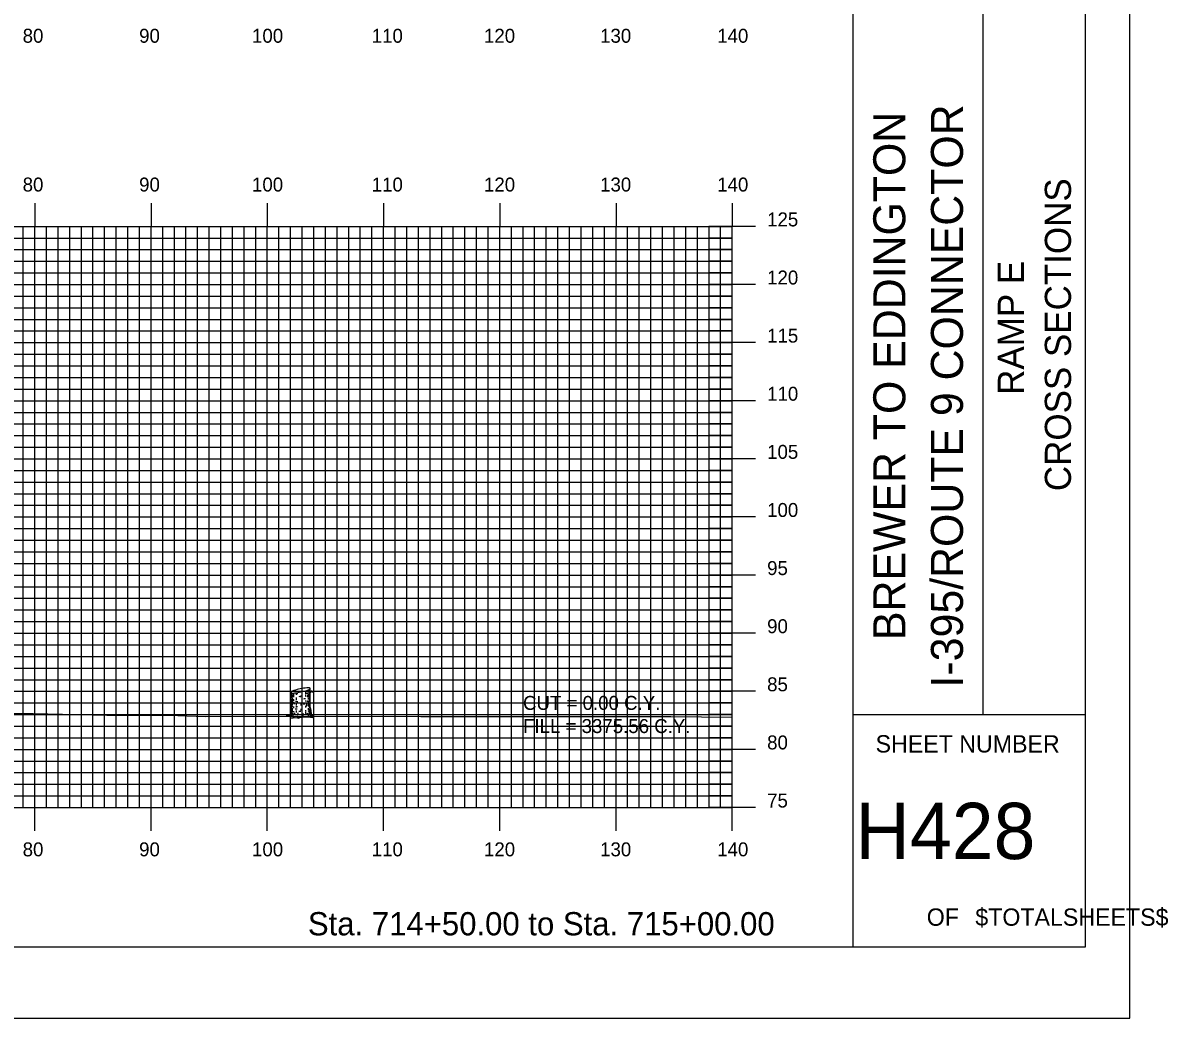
# Model space of a CAD drawing. Extents: x 856084 to 856427, y 364366 to 364586.
# Drawn here: x 856328.8 to 856427.3, y 364365.7 to 364451.3 of the extents above; entities that cross this region are included whole.
import ezdxf

# ---------------------------------------------------------------- set-up
doc = ezdxf.new("R2010")
doc.units = 0
for name, color, linetype in [('BORDER', 7, 'Continuous'), ('D_Text_Standard', 7, 'Continuous'), ('H_V ANNOTATION', 7, 'Continuous'), ('M_Trees_Conifer_Pay', 7, 'Continuous'), ('MAJOR', 7, 'Continuous'), ('MINOR', 7, 'Continuous'), ('PLOT BOUNDARY', 7, 'Continuous'), ('S_Roadway_Centerline', 7, 'Continuous')]:
    doc.layers.add(name, color=color, linetype=linetype)

msp = doc.modelspace()

# ---------------------------------------------------------------- linework, layer by layer
at = {"layer": 'BORDER'}
for p, q in [((856400.196, 364371.787), (856400.196, 364581.787)), ((856411.378, 364391.793), (856411.378, 364461.793)), ((856400.196, 364391.793), (856420.196, 364391.793))]:
    msp.add_line(p, q, dxfattribs=at)
msp.add_lwpolyline([(856100.196, 364371.787), (856420.196, 364371.787), (856420.196, 364581.787), (856100.196, 364581.787)], close=True, dxfattribs=at)
at = {"layer": 'M_Trees_Conifer_Pay'}
for p, q in [((856353.421, 364393.959), (856353.421, 364393.796)), ((856353.492, 364392.384), (856353.492, 364394.031)), ((856351.828, 364391.974), (856351.828, 364393.696)), ((856351.876, 364393.658), (856351.876, 364393.187)), ((856351.876, 364393.123), (856351.876, 364392.814)), ((856351.934, 364393.647), (856351.934, 364393.549)), ((856351.934, 364393.475), (856351.934, 364393.271)), ((856351.934, 364393.213), (856351.934, 364393.014)), ((856351.934, 364392.967), (856351.934, 364392.631)), ((856352.059, 364393.639), (856352.059, 364393.407)), ((856352.059, 364393.366), (856352.059, 364393.292)), ((856352.279, 364393.659), (856352.279, 364393.491)), ((856352.279, 364393.255), (856352.279, 364393.018)), ((856352.685, 364393.428), (856352.685, 364393.333)), ((856353.075, 364393.701), (856353.075, 364393.502)), ((856353.075, 364393.444), (856353.075, 364393.356)), ((856353.075, 364393.008), (856353.075, 364392.903)), ((856353.304, 364393.898), (856353.304, 364393.675)), ((856353.304, 364393.586), (856353.304, 364393.539)), ((856353.304, 364393.203), (856353.304, 364393.072)), ((856353.304, 364392.961), (856353.304, 364392.851)), ((856353.361, 364393.403), (856353.309, 364393.343)), ((856353.421, 364393.728), (856353.421, 364393.6)), ((856353.421, 364393.413), (856353.421, 364393.077)), ((856353.421, 364393.041), (856353.421, 364392.878)), ((856351.876, 364392.767), (856351.876, 364392.275)), ((856351.876, 364392.221), (856351.876, 364391.974)), ((856351.934, 364392.577), (856351.934, 364392.442)), ((856351.934, 364392.343), (856351.934, 364391.964)), ((856352.059, 364392.888), (856352.059, 364392.75)), ((856352.059, 364392.478), (856352.059, 364392.337)), ((856352.059, 364392.075), (856352.059, 364391.98)), ((856352.279, 364392.773), (856352.279, 364392.621)), ((856352.279, 364392.577), (856352.279, 364392.404)), ((856352.279, 364392.127), (856352.279, 364391.974)), ((856352.685, 364392.814), (856352.685, 364392.74)), ((856352.685, 364392.715), (856352.685, 364392.567)), ((856352.685, 364392.275), (856352.685, 364392.122)), ((856353.075, 364392.536), (856353.075, 364392.39)), ((856353.075, 364392.157), (856353.075, 364392.069)), ((856353.304, 364392.715), (856353.304, 364392.573)), ((856353.304, 364392.346), (856353.304, 364392.174)), ((856353.421, 364392.831), (856353.421, 364392.614)), ((856353.421, 364392.583), (856353.421, 364392.509)), ((856353.421, 364392.469), (856353.421, 364392.295)), ((856352.059, 364391.581), (856352.222, 364391.644)), ((856352.496, 364391.516), (856352.37, 364391.581))]:
    msp.add_line(p, q, dxfattribs=at)
for points in [[(856352.008, 364393.001), (856352.002, 364393.096), (856352.045, 364393.073), (856352.045, 364392.979)], [(856353.276, 364393.491), (856353.245, 364393.407), (856353.241, 364393.339), (856353.272, 364393.276)], [(856353.309, 364393.529), (856353.346, 364393.455), (856353.393, 364393.512), (856353.451, 364393.58), (856353.544, 364393.774), (856353.608, 364393.821), (856353.639, 364393.827)], [(856353.324, 364393.276), (856353.361, 364393.403), (856353.424, 364393.518), (856353.455, 364393.586), (856353.524, 364393.732)], [(856353.538, 364393.762), (856353.614, 364393.77), (856353.686, 364393.671)], [(856353.492, 364392.384), (856353.544, 364392.122), (856353.56, 364391.848), (856353.618, 364391.723), (856353.754, 364391.692), (856353.523, 364391.655), (856353.523, 364391.655), (856353.529, 364391.608), (856353.777, 364391.513), (856353.502, 364391.53), (856353.147, 364391.55), (856352.825, 364391.539), (856352.832, 364391.622), (856352.683, 364391.539), (856352.496, 364391.516), (856352.521, 364391.449), (856352.253, 364391.492), (856352.033, 364391.465), (856351.74, 364391.482), (856352.029, 364391.539), (856352.059, 364391.581), (856351.897, 364391.638), (856351.66, 364391.649), (856351.419, 364391.649), (856351.761, 364391.707), (856351.802, 364391.787), (856351.828, 364391.974)], [(856353.082, 364391.991), (856353.093, 364391.865), (856353.167, 364391.822)], [(856353.147, 364392.602), (856353.159, 364392.526), (856353.206, 364392.536), (856353.194, 364392.703)], [(856353.319, 364392.096), (856353.393, 364391.991), (856353.398, 364391.818), (856353.523, 364391.655)], [(856353.418, 364392.241), (856353.424, 364392.096), (856353.471, 364392.028), (856353.482, 364391.828)], [(856351.876, 364391.927), (856351.855, 364391.848), (856351.835, 364391.754)], [(856351.954, 364391.906), (856351.96, 364391.791), (856351.907, 364391.702), (856351.897, 364391.638)], [(856352.117, 364391.933), (856352.117, 364391.801), (856352.029, 364391.702)], [(856352.344, 364391.692), (856352.411, 364391.787), (856352.438, 364391.927)], [(856352.832, 364391.622), (856352.906, 364391.764), (856352.916, 364391.865)], [(856353.361, 364391.602), (856353.346, 364391.74), (856353.272, 364391.869)]]:
    msp.add_lwpolyline(points, dxfattribs=at)
for centre, radius, start, end in [((856353.684, 364388.928), 5.179, 101.7194, 108.05939), ((856353.684, 364388.928), 5.179, 95.37941, 101.7194), ((856353.274, 364393.286), 0.802, 79.2194, 95.37941), ((856352.994, 364394.637), 0.802, 288.05939, 304.2194), ((856353.377, 364393.827), 0.251, 71.05013, 79.2194), ((856353.304, 364394.181), 0.251, 304.2194, 312.38868), ((856353.432, 364393.987), 0.0817, 56.7194, 71.05013), ((856353.417, 364394.056), 0.0817, 312.38868, 326.7194), ((856353.448, 364394.011), 0.0527, 46.92298, 56.7194), ((856353.462, 364394.027), 0.0314, 34.2194, 46.92298), ((856353.442, 364394.04), 0.0527, 326.7194, 336.51582), ((856353.466, 364394.03), 0.0264, 23.40735, 34.2194), ((856353.461, 364394.032), 0.0314, 336.51582, 349.2194), ((856353.47, 364394.031), 0.0226, 11.7194, 23.40735), ((856353.47, 364394.031), 0.0226, 0.03145, 11.7194), ((856353.466, 364394.031), 0.0264, 349.2194, 0.03145), ((856351.861, 364393.517), 0.0334, 163.94846, 180), ((856351.861, 364393.517), 0.0334, 180, 196.05154), ((856351.861, 364393.07), 0.0334, 163.94846, 180), ((856351.861, 364393.07), 0.0334, 180, 196.05154), ((856351.86, 364393.694), 0.0314, 156.51582, 169.2194), ((856351.855, 364393.695), 0.0264, 169.2194, 180.03145), ((856351.851, 364393.695), 0.0226, 180.03145, 191.7194), ((856351.851, 364393.695), 0.0226, 191.7194, 203.40735), ((856351.871, 364393.52), 0.0441, 196.05154, 210), ((856351.871, 364393.073), 0.0441, 196.05154, 210), ((856351.855, 364393.697), 0.0264, 203.40735, 214.2194), ((856351.879, 364393.686), 0.0527, 146.7194, 156.51582), ((856351.859, 364393.7), 0.0314, 214.2194, 226.92298), ((856351.887, 364393.529), 0.0624, 210, 228.74941), ((856351.887, 364393.083), 0.0624, 210, 228.74941), ((856351.904, 364393.67), 0.0817, 132.38868, 146.7194), ((856351.873, 364393.715), 0.0527, 226.92298, 236.7194), ((856351.889, 364393.739), 0.0817, 236.7194, 251.05013), ((856351.959, 364393.612), 0.172, 228.74941, 240), ((856351.959, 364393.165), 0.172, 228.74941, 240), ((856352.018, 364393.545), 0.251, 124.2194, 132.38868), ((856351.944, 364393.899), 0.251, 251.05013, 259.2194), ((856352.158, 364393.957), 0.571, 240, 240.33672), ((856352.158, 364393.51), 0.571, 240, 240.33672), ((856352.16, 364393.746), 0.571, 240, 247.05866), ((856352.327, 364393.09), 0.802, 108.05939, 124.2194), ((856352.047, 364394.44), 0.802, 259.2194, 275.37941), ((856352.158, 364393.957), 0.571, 246.85973, 257.98457), ((856351.637, 364398.798), 5.179, 275.37941, 281.7194), ((856352.659, 364397.028), 4.124, 264.08098, 266.66759), ((856352.661, 364397.707), 4.124, 264.6955, 266.73309), ((856352.659, 364397.475), 4.124, 268.07512, 270), ((856352.659, 364397.475), 4.124, 270, 270.35814), ((856351.637, 364398.798), 5.179, 281.7194, 288.05939), ((856352.661, 364397.264), 4.124, 273.70524, 275.95043), ((856352.659, 364397.475), 4.124, 275.78493, 277.05584), ((856352.661, 364397.707), 4.124, 276.23804, 278.1032), ((856352.659, 364397.028), 4.124, 277.61247, 278.1032), ((856353.16, 364393.51), 0.571, 278.1032, 286.92962), ((856353.162, 364394.19), 0.571, 278.1032, 284.36665), ((856353.162, 364394.344), 0.571, 284.43166, 292.41325), ((856353.161, 364393.746), 0.571, 284.44928, 297.04285), ((856353.162, 364394.19), 0.571, 297.0237, 300), ((856353.16, 364393.51), 0.571, 297.18959, 300), ((856353.359, 364393.165), 0.172, 300, 311.25059), ((856353.361, 364393.999), 0.172, 300, 311.25059), ((856353.361, 364393.845), 0.172, 300, 311.25059), ((856353.432, 364393.083), 0.0624, 311.25059, 330), ((856353.433, 364393.917), 0.0624, 311.25059, 330), ((856353.433, 364393.762), 0.0624, 311.25059, 330), ((856353.448, 364393.073), 0.0441, 330, 343.94846), ((856353.449, 364393.908), 0.0441, 330, 343.94846), ((856353.449, 364393.753), 0.0441, 330, 343.94846), ((856353.458, 364393.07), 0.0334, 343.94846, 354.21506), ((856353.459, 364393.905), 0.0334, 343.94846, 354.21506), ((856353.459, 364393.75), 0.0334, 343.94846, 354.21506), ((856353.459, 364393.306), 0.0334, 343.94846, 354.21506), ((856351.861, 364392.86), 0.0334, 163.94846, 180), ((856351.861, 364392.86), 0.0334, 180, 196.05154), ((856351.861, 364392.624), 0.0334, 163.94846, 180), ((856351.861, 364392.624), 0.0334, 180, 196.05154), ((856351.861, 364392.426), 0.0334, 163.94846, 180), ((856351.861, 364392.23), 0.0334, 163.94846, 180), ((856351.861, 364392.23), 0.0334, 180, 196.05154), ((856351.861, 364392.01), 0.0334, 163.94846, 180), ((856351.861, 364392.01), 0.0334, 180, 196.05154), ((856351.871, 364392.863), 0.0441, 196.05154, 210), ((856351.871, 364392.627), 0.0441, 196.05154, 210), ((856351.871, 364392.233), 0.0441, 196.05154, 210), ((856351.871, 364392.013), 0.0441, 196.05154, 210), ((856351.887, 364392.873), 0.0624, 210, 228.74941), ((856351.887, 364392.636), 0.0624, 210, 228.74941), ((856351.887, 364392.243), 0.0624, 210, 228.74941), ((856351.887, 364392.022), 0.0624, 210, 228.74941), ((856351.959, 364392.955), 0.172, 228.74941, 240), ((856351.959, 364392.718), 0.172, 228.74941, 240), ((856351.959, 364392.325), 0.172, 228.74941, 240), ((856351.959, 364392.105), 0.172, 228.74941, 240), ((856352.158, 364393.3), 0.571, 240, 246.85973), ((856352.158, 364393.063), 0.571, 240, 246.85973), ((856352.148, 364392.872), 0.571, 241.23686, 248.02677), ((856352.158, 364392.67), 0.571, 240, 246.85973), ((856352.158, 364392.45), 0.571, 240, 244.53138), ((856352.158, 364393.3), 0.571, 259.27072, 261.8968), ((856352.659, 364396.818), 4.124, 261.8968, 263.14738), ((856352.659, 364396.383), 4.124, 263.49906, 265.83975), ((856352.659, 364396.581), 4.124, 264.71603, 266.31934), ((856352.659, 364396.188), 4.124, 267.81166, 270), ((856352.659, 364396.818), 4.124, 270, 270.35814), ((856352.659, 364396.188), 4.124, 270, 270.13279), ((856352.659, 364396.818), 4.124, 273.14934, 275.45691), ((856352.659, 364396.188), 4.124, 275.78493, 276.78961), ((856353.16, 364393.063), 0.571, 285.39827, 297.18959), ((856353.16, 364392.67), 0.571, 288.50673, 297.27208), ((856353.16, 364392.866), 0.571, 289.29072, 300), ((856353.16, 364393.3), 0.571, 297.18959, 300), ((856353.359, 364392.955), 0.172, 300, 311.25059), ((856353.359, 364392.521), 0.172, 300, 311.25059), ((856353.359, 364392.105), 0.172, 300, 311.25059), ((856353.432, 364392.873), 0.0624, 311.25059, 330), ((856353.432, 364392.438), 0.0624, 311.25059, 330), ((856353.432, 364392.022), 0.0624, 311.25059, 330), ((856353.448, 364392.863), 0.0441, 330, 343.94846), ((856353.448, 364392.429), 0.0441, 330, 343.94846), ((856353.448, 364392.013), 0.0441, 330, 343.94846), ((856353.458, 364392.86), 0.0334, 343.94846, 354.21506), ((856353.458, 364392.426), 0.0334, 343.94846, 354.21506), ((856353.458, 364392.01), 0.0334, 343.94846, 354.21506), ((856352.659, 364395.967), 4.124, 262.44379, 263.51202), ((856352.659, 364395.967), 4.124, 277.36842, 278.1032), ((856353.16, 364392.45), 0.571, 278.1032, 281.63703)]:
    msp.add_arc(centre, radius, start, end, dxfattribs=at)
at = {"layer": 'MAJOR'}
for p, q in [((856329.796, 364435.791), (856329.796, 364433.787)), ((856339.796, 364435.791), (856339.796, 364433.787)), ((856349.796, 364435.791), (856349.796, 364433.787)), ((856359.796, 364435.791), (856359.796, 364433.787)), ((856369.796, 364435.791), (856369.796, 364433.787)), ((856379.796, 364435.791), (856379.796, 364433.787)), ((856389.796, 364435.791), (856389.796, 364433.787)), ((856109.796, 364433.787), (856389.796, 364433.787)), ((856109.796, 364433.787), (856389.796, 364433.787)), ((856329.796, 364383.787), (856329.796, 364433.787)), ((856339.796, 364383.787), (856339.796, 364433.787)), ((856349.796, 364383.787), (856349.796, 364433.787)), ((856359.796, 364383.787), (856359.796, 364433.787)), ((856369.796, 364383.787), (856369.796, 364433.787)), ((856379.796, 364383.787), (856379.796, 364433.787)), ((856391.8, 364433.787), (856387.792, 364433.787)), ((856389.796, 364383.787), (856389.796, 364433.787)), ((856389.796, 364383.787), (856389.796, 364433.787)), ((856109.796, 364428.787), (856389.796, 364428.787)), ((856391.8, 364428.787), (856387.792, 364428.787)), ((856109.796, 364423.787), (856389.796, 364423.787)), ((856391.8, 364423.787), (856387.792, 364423.787)), ((856109.796, 364418.787), (856389.796, 364418.787)), ((856391.8, 364418.787), (856387.792, 364418.787)), ((856109.796, 364413.787), (856389.796, 364413.787)), ((856391.8, 364413.787), (856387.792, 364413.787)), ((856109.796, 364408.787), (856389.796, 364408.787)), ((856391.8, 364408.787), (856387.792, 364408.787)), ((856109.796, 364403.787), (856389.796, 364403.787)), ((856391.8, 364403.787), (856387.792, 364403.787)), ((856109.796, 364398.787), (856389.796, 364398.787)), ((856391.8, 364398.787), (856387.792, 364398.787)), ((856109.796, 364393.787), (856389.796, 364393.787)), ((856391.8, 364393.787), (856387.792, 364393.787)), ((856109.796, 364388.787), (856389.796, 364388.787)), ((856391.8, 364388.787), (856387.792, 364388.787)), ((856109.796, 364383.787), (856389.796, 364383.787)), ((856109.796, 364383.787), (856389.796, 364383.787)), ((856329.796, 364381.783), (856329.796, 364383.787)), ((856339.796, 364381.783), (856339.796, 364383.787)), ((856349.796, 364381.783), (856349.796, 364383.787)), ((856359.796, 364381.783), (856359.796, 364383.787)), ((856369.796, 364381.783), (856369.796, 364383.787)), ((856379.796, 364381.783), (856379.796, 364383.787)), ((856391.8, 364383.787), (856387.792, 364383.787)), ((856389.796, 364381.783), (856389.796, 364383.787))]:
    msp.add_line(p, q, dxfattribs=at)
at = {"layer": 'MINOR'}
for p, q in [((856328.796, 364383.787), (856328.796, 364433.787)), ((856330.796, 364383.787), (856330.796, 364433.787)), ((856331.796, 364383.787), (856331.796, 364433.787)), ((856332.796, 364383.787), (856332.796, 364433.787)), ((856333.796, 364383.787), (856333.796, 364433.787)), ((856334.796, 364383.787), (856334.796, 364433.787)), ((856335.796, 364383.787), (856335.796, 364433.787)), ((856336.796, 364383.787), (856336.796, 364433.787)), ((856337.796, 364383.787), (856337.796, 364433.787)), ((856338.796, 364383.787), (856338.796, 364433.787)), ((856340.796, 364383.787), (856340.796, 364433.787)), ((856341.796, 364383.787), (856341.796, 364433.787)), ((856342.796, 364383.787), (856342.796, 364433.787)), ((856343.796, 364383.787), (856343.796, 364433.787)), ((856344.796, 364383.787), (856344.796, 364433.787)), ((856345.796, 364383.787), (856345.796, 364433.787)), ((856346.796, 364383.787), (856346.796, 364433.787)), ((856347.796, 364383.787), (856347.796, 364433.787)), ((856348.796, 364383.787), (856348.796, 364433.787)), ((856350.796, 364383.787), (856350.796, 364433.787)), ((856351.796, 364383.787), (856351.796, 364433.787)), ((856352.796, 364383.787), (856352.796, 364433.787)), ((856353.796, 364383.787), (856353.796, 364433.787)), ((856354.796, 364383.787), (856354.796, 364433.787)), ((856355.796, 364383.787), (856355.796, 364433.787)), ((856356.796, 364383.787), (856356.796, 364433.787)), ((856357.796, 364383.787), (856357.796, 364433.787)), ((856358.796, 364383.787), (856358.796, 364433.787)), ((856360.796, 364383.787), (856360.796, 364433.787)), ((856361.796, 364383.787), (856361.796, 364433.787)), ((856362.796, 364383.787), (856362.796, 364433.787)), ((856363.796, 364383.787), (856363.796, 364433.787)), ((856364.796, 364383.787), (856364.796, 364433.787)), ((856365.796, 364383.787), (856365.796, 364433.787)), ((856366.796, 364383.787), (856366.796, 364433.787)), ((856367.796, 364383.787), (856367.796, 364433.787)), ((856368.796, 364383.787), (856368.796, 364433.787)), ((856370.796, 364383.787), (856370.796, 364433.787)), ((856371.796, 364383.787), (856371.796, 364433.787)), ((856372.796, 364383.787), (856372.796, 364433.787)), ((856373.796, 364383.787), (856373.796, 364433.787)), ((856374.796, 364383.787), (856374.796, 364433.787)), ((856375.796, 364383.787), (856375.796, 364433.787)), ((856376.796, 364383.787), (856376.796, 364433.787)), ((856377.796, 364383.787), (856377.796, 364433.787)), ((856378.796, 364383.787), (856378.796, 364433.787)), ((856380.796, 364383.787), (856380.796, 364433.787)), ((856381.796, 364383.787), (856381.796, 364433.787)), ((856382.796, 364383.787), (856382.796, 364433.787)), ((856383.796, 364383.787), (856383.796, 364433.787)), ((856384.796, 364383.787), (856384.796, 364433.787)), ((856385.796, 364383.787), (856385.796, 364433.787)), ((856386.796, 364383.787), (856386.796, 364433.787)), ((856387.796, 364383.787), (856387.796, 364433.787)), ((856388.796, 364383.787), (856388.796, 364433.787)), ((856109.796, 364432.787), (856389.796, 364432.787)), ((856389.796, 364432.787), (856387.792, 364432.787)), ((856109.796, 364431.787), (856389.796, 364431.787)), ((856389.796, 364431.787), (856387.792, 364431.787)), ((856109.796, 364430.787), (856389.796, 364430.787)), ((856389.796, 364430.787), (856387.792, 364430.787)), ((856109.796, 364429.787), (856389.796, 364429.787)), ((856389.796, 364429.787), (856387.792, 364429.787)), ((856109.796, 364427.787), (856389.796, 364427.787)), ((856389.796, 364427.787), (856387.792, 364427.787)), ((856109.796, 364426.787), (856389.796, 364426.787)), ((856389.796, 364426.787), (856387.792, 364426.787)), ((856109.796, 364425.787), (856389.796, 364425.787)), ((856389.796, 364425.787), (856387.792, 364425.787)), ((856109.796, 364424.787), (856389.796, 364424.787)), ((856389.796, 364424.787), (856387.792, 364424.787)), ((856109.796, 364422.787), (856389.796, 364422.787)), ((856389.796, 364422.787), (856387.792, 364422.787)), ((856109.796, 364421.787), (856389.796, 364421.787)), ((856389.796, 364421.787), (856387.792, 364421.787)), ((856109.796, 364420.787), (856389.796, 364420.787)), ((856389.796, 364420.787), (856387.792, 364420.787)), ((856109.796, 364419.787), (856389.796, 364419.787)), ((856389.796, 364419.787), (856387.792, 364419.787)), ((856109.796, 364417.787), (856389.796, 364417.787)), ((856389.796, 364417.787), (856387.792, 364417.787)), ((856109.796, 364416.787), (856389.796, 364416.787)), ((856389.796, 364416.787), (856387.792, 364416.787)), ((856109.796, 364415.787), (856389.796, 364415.787)), ((856389.796, 364415.787), (856387.792, 364415.787)), ((856109.796, 364414.787), (856389.796, 364414.787)), ((856389.796, 364414.787), (856387.792, 364414.787)), ((856109.796, 364412.787), (856389.796, 364412.787)), ((856389.796, 364412.787), (856387.792, 364412.787)), ((856109.796, 364411.787), (856389.796, 364411.787)), ((856389.796, 364411.787), (856387.792, 364411.787)), ((856109.796, 364410.787), (856389.796, 364410.787)), ((856389.796, 364410.787), (856387.792, 364410.787)), ((856109.796, 364409.787), (856389.796, 364409.787)), ((856389.796, 364409.787), (856387.792, 364409.787)), ((856109.796, 364407.787), (856389.796, 364407.787)), ((856389.796, 364407.787), (856387.792, 364407.787)), ((856109.796, 364406.787), (856389.796, 364406.787)), ((856389.796, 364406.787), (856387.792, 364406.787)), ((856109.796, 364405.787), (856389.796, 364405.787)), ((856389.796, 364405.787), (856387.792, 364405.787)), ((856109.796, 364404.787), (856389.796, 364404.787)), ((856389.796, 364404.787), (856387.792, 364404.787)), ((856109.796, 364402.787), (856389.796, 364402.787)), ((856389.796, 364402.787), (856387.792, 364402.787)), ((856109.796, 364401.787), (856389.796, 364401.787)), ((856389.796, 364401.787), (856387.792, 364401.787)), ((856109.796, 364400.787), (856389.796, 364400.787)), ((856389.796, 364400.787), (856387.792, 364400.787)), ((856109.796, 364399.787), (856389.796, 364399.787)), ((856389.796, 364399.787), (856387.792, 364399.787)), ((856109.796, 364397.787), (856389.796, 364397.787)), ((856389.796, 364397.787), (856387.792, 364397.787)), ((856109.796, 364396.787), (856389.796, 364396.787)), ((856389.796, 364396.787), (856387.792, 364396.787)), ((856109.796, 364395.787), (856389.796, 364395.787)), ((856389.796, 364395.787), (856387.792, 364395.787)), ((856109.796, 364394.787), (856389.796, 364394.787)), ((856389.796, 364394.787), (856387.792, 364394.787)), ((856109.796, 364392.787), (856389.796, 364392.787)), ((856389.796, 364392.787), (856387.792, 364392.787)), ((856109.796, 364391.787), (856389.796, 364391.787)), ((856389.796, 364391.787), (856387.792, 364391.787)), ((856109.796, 364390.787), (856389.796, 364390.787)), ((856389.796, 364390.787), (856387.792, 364390.787)), ((856109.796, 364389.787), (856389.796, 364389.787)), ((856389.796, 364389.787), (856387.792, 364389.787)), ((856109.796, 364387.787), (856389.796, 364387.787)), ((856389.796, 364387.787), (856387.792, 364387.787)), ((856109.796, 364386.787), (856389.796, 364386.787)), ((856389.796, 364386.787), (856387.792, 364386.787)), ((856109.796, 364385.787), (856389.796, 364385.787)), ((856389.796, 364385.787), (856387.792, 364385.787)), ((856109.796, 364384.787), (856389.796, 364384.787)), ((856389.796, 364384.787), (856387.792, 364384.787))]:
    msp.add_line(p, q, dxfattribs=at)
at = {"layer": 'PLOT BOUNDARY'}
msp.add_lwpolyline([(856084.009, 364365.669), (856424.009, 364365.669), (856424.009, 364585.669), (856084.009, 364585.669)], close=True, dxfattribs=at)
at = {"layer": 'S_Roadway_Centerline'}
msp.add_lwpolyline([(856327.033, 364391.902), (856329.64, 364391.869), (856335.998, 364391.732), (856342.09, 364391.693), (856344.462, 364391.623), (856351.912, 364391.633), (856363.015, 364391.621), (856366.51, 364391.608), (856374.005, 364391.626), (856378.893, 364391.624), (856381.21, 364391.607), (856384.502, 364391.608), (856389.796, 364391.571)], dxfattribs=at)

# ---------------------------------------------------------------- texts
at = {"layer": 'BORDER'}
for s, height, p in [('BREWER TO EDDINGTON', 2.75575, (856404.685, 364398.196)), ('I-395/ROUTE 9 CONNECTOR', 2.75575, (856409.645, 364394.117)), ('CROSS SECTIONS', 2.25, (856418.937, 364411.009)), ('RAMP E', 2.25, (856414.887, 364419.291))]:
    msp.add_text(s, height=height, rotation=90, dxfattribs=at).set_placement(p)
for s, height, p in [('SHEET NUMBER', 1.49054, (856402.127, 364388.52)), ('H428', 4.8388, (856400.407, 364379.352)), ('$TOTALSHEETS$', 1.49054, (856410.709, 364373.613)), ('OF', 1.4905, (856406.53, 364373.613))]:
    msp.add_text(s, height=height, dxfattribs=at).set_placement(p)
at = {"layer": 'D_Text_Standard'}
for s, p in [('CUT = 0.00 C.Y.', (856371.796, 364392.187)), ('FILL = 3375.56 C.Y.', (856371.796, 364390.195))]:
    msp.add_text(s, height=1.2, dxfattribs=at).set_placement(p)
at = {"layer": 'H_V ANNOTATION'}
for s, height, p in [('80', 1.2, (856328.747, 364449.587)), ('90', 1.2, (856338.768, 364449.587)), ('100', 1.2, (856348.48, 364449.587)), ('110', 1.2, (856358.779, 364449.587)), ('120', 1.2, (856368.437, 364449.587)), ('130', 1.2, (856378.426, 364449.587)), ('140', 1.2, (856388.501, 364449.587)), ('80', 1.2, (856328.747, 364436.787)), ('90', 1.2, (856338.768, 364436.787)), ('100', 1.2, (856348.48, 364436.787)), ('110', 1.2, (856358.779, 364436.787)), ('120', 1.2, (856368.437, 364436.787)), ('130', 1.2, (856378.426, 364436.787)), ('140', 1.2, (856388.501, 364436.787)), ('125', 1.2, (856392.796, 364433.787)), ('120', 1.2, (856392.796, 364428.787)), ('115', 1.2, (856392.796, 364423.787)), ('110', 1.2, (856392.796, 364418.787)), ('105', 1.2, (856392.796, 364413.787)), ('100', 1.2, (856392.796, 364408.787)), ('95', 1.2, (856392.796, 364403.787)), ('90', 1.2, (856392.796, 364398.787)), ('85', 1.2, (856392.796, 364393.787)), ('80', 1.2, (856392.796, 364388.787)), ('75', 1.2, (856392.796, 364383.787)), ('80', 1.2, (856328.747, 364379.587)), ('90', 1.2, (856338.768, 364379.587)), ('100', 1.2, (856348.48, 364379.587)), ('110', 1.2, (856358.779, 364379.587)), ('120', 1.2, (856368.437, 364379.587)), ('130', 1.2, (856378.426, 364379.587)), ('140', 1.2, (856388.501, 364379.587)), ('Sta. 714+50.00 to Sta. 715+00.00', 2.0004, (856353.288, 364372.787))]:
    msp.add_text(s, height=height, dxfattribs=at).set_placement(p)

doc.saveas('drawing.dxf')
